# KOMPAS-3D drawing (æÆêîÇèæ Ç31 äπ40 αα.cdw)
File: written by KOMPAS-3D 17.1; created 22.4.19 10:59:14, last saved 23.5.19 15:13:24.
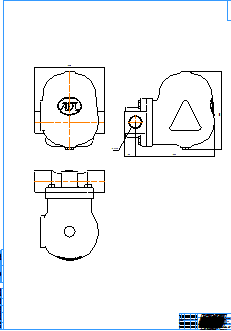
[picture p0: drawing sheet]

Sheet 1: A0, portrait

Title block, sheet 1: name: СТИМАКС А31 Ду40 р/р; material: Внимание! Данный продукт является объектом авторского права ООО «Торговый Дом АДЛ». / Запрещается изменение, копирование, распространение / (в том числе путем копирования на другие сайты и ресурсы в Интернете) / или любое иное использование информации и объектов без предварительного / согласия правообладателя (ООО «Торговый Дом АДЛ»).; mass: 31; sheets: 1; organisation: ООО "Торговый дом АДЛ"; sheet format: A0; stored path: \\adlc.lan\data\АДЛ_ПКД\3D-модели\ADL production\Конденсатоотводчики СТИМАКС\Поплавковые\Серия А31\KOMPAS 2D\СТИМАКС А31 Ду40 рр.cdw

Views: Вид 1, Проекционный вид 2, Проекционный вид 3
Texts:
  user
Dimensions and other numbers on the sheet: 250; 40; 284; 280; 1:1; 1; 31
